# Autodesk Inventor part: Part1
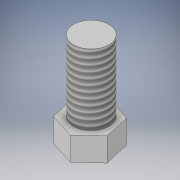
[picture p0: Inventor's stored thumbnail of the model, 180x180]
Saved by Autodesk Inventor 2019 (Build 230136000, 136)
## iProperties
Created: 2019-10
Part Number: Part1
Material: Generic
Document SubType Name: Sheet Metal
Designer: PRADYUMNA
Density: 1 g/cm^3
Sheet Metal Rule: Default_mm
Appearance: Default
Author: PRADYUMNA
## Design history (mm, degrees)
node "Face1"
  sketch "Sketch1"
    geometry: L1 (1.062, 0.466)-(0.578, 2.606); L2 (0.578, 2.606)-(2.188, 4.096); L3 (2.188, 4.096)-(4.284, 3.446); L4 (4.284, 3.446)-(4.768, 1.306); L5 (4.768, 1.306)-(3.158, -0.184); L6 (3.158, -0.184)-(1.062, 0.466); 2 further points
    constraints: 12 end point, 13 other
    dimensions: "d0" = 3.8 distance between parallel lines of L1 L4
sketch "Sketch2"
  geometry: C1 r 1.5 at (-2.695, -1.832); 1 further point
  constraints: 1 centre point
  dimensions: "d2" = 3 diameter of C1
extrude "Extrusion1" join sketch "Sketch2" distance "d3" = 6; taper "d4" = 0 deg
thread "Thread1" dims "d5" = 10, "d6" = 0
body "Solid1"
face "Plate1" dims "d1" = 2 (= Thickness)
other parameters: "Thickness" = 2 (derived), "BendRadius" = 2 (= Thickness), "BendReliefWidth" = 2 (= Thickness), "BendReliefDepth" = 1 (= 0.5 x Thickness), "CornerReliefSize" = 8 (= 4 x Thickness), "SeamGap" = 0.01, "MinimumRemnant" = 4 (= 2 x Thickness), "TransitionRadius" = 2 (= BendRadius), "JacobiRadiusSize" = 2 (= BendRadius), "GapSize" = 2 (= Thickness)
